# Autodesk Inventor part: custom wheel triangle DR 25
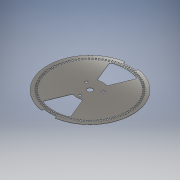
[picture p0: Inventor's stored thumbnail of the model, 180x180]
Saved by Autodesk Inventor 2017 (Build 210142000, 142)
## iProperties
Created: 2016-09
Part Number: custom wheel triangle DR 25
Material: Generic
Document SubType Name: Modeling
Designer: Radek
Density: 1 g/cm^3
Appearance: Mirror
Author: Radek
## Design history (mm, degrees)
workplane "Work Plane1"
sketch "Sketch1"
  geometry: L1 (-46.781, 4.422)-(-44.253, 4.183) reference; L2 (-44.362, 2.791)-(-46.897, 2.951) reference; L3 (-46.411, 7.351)-(-43.903, 6.954) reference; L4 (-44.099, 5.571)-(-46.619, 5.889) reference; L5 (-45.858, 10.251)-(-43.38, 9.696) reference; L6 (-43.663, 8.329)-(-46.158, 8.805) reference; L7 (-45.124, 13.11)-(-42.685, 12.401) reference; L8 (-43.054, 11.054)-(-45.514, 11.686) reference; L9 (-44.212, 15.917)-(-41.822, 15.057) reference; L10 (-42.274, 13.736)-(-44.69, 14.521) reference; L11 (-43.125, 18.662)-(-40.794, 17.653) reference; L12 (-41.329, 16.363)-(-43.69, 17.298) reference; L13 (-41.868, 21.333)-(-39.605, 20.18) reference; L14 (-40.22, 18.926)-(-42.518, 20.007) reference; L15 (-40.446, 23.92)-(-38.26, 22.627) reference; L16 (-38.952, 21.414)-(-41.178, 22.638) reference; L17 (-38.865, 26.412)-(-36.764, 24.985) reference; L18 (-37.53, 23.818)-(-39.675, 25.179) reference; L19 (-37.129, 28.801)-(-35.122, 27.244) reference; L20 (-35.961, 26.127)-(-38.016, 27.62) reference; L21 (-35.248, 31.075)-(-33.342, 29.395) reference; L22 (-34.249, 28.333)-(-36.206, 29.953) reference; L23 (-33.227, 33.227)-(-31.431, 31.431) reference; L24 (-32.403, 30.428)-(-34.254, 32.167) reference; L25 (-31.075, 35.248)-(-29.395, 33.342) reference; L26 (-30.428, 32.403)-(-32.167, 34.254) reference; L27 (-28.801, 37.129)-(-27.244, 35.122) reference; L28 (-28.333, 34.249)-(-29.953, 36.206) reference; L29 (-26.412, 38.865)-(-24.985, 36.764) reference; L30 (-26.127, 35.961)-(-27.62, 38.016) reference; L31 (-23.92, 40.446)-(-22.627, 38.26) reference; L32 (-23.818, 37.53)-(-25.179, 39.675) reference; L33 (-21.333, 41.868)-(-20.18, 39.605) reference; L34 (-21.414, 38.952)-(-22.638, 41.178) reference; L35 (-18.662, 43.125)-(-17.653, 40.794) reference; L36 (-18.926, 40.22)-(-20.007, 42.518) reference; L37 (-15.917, 44.212)-(-15.057, 41.822) reference; L38 (-16.363, 41.329)-(-17.298, 43.69) reference; L39 (-13.11, 45.124)-(-12.401, 42.685) reference; L40 (-13.736, 42.274)-(-14.521, 44.69) reference; L41 (-10.251, 45.858)-(-9.696, 43.38) reference; L42 (-11.054, 43.054)-(-11.686, 45.514) reference; L43 (-7.351, 46.411)-(-6.954, 43.903) reference; L44 (-8.329, 43.663)-(-8.805, 46.158) reference; L45 (-4.422, 46.781)-(-4.183, 44.253) reference; L46 (-5.571, 44.099)-(-5.889, 46.619) reference; L47 (-1.476, 46.967)-(-1.396, 44.428) reference; L48 (-2.791, 44.362)-(-2.951, 46.897) reference; L49 (1.476, 46.967)-(1.396, 44.428) reference; L50 (0, 44.45)-(0, 46.99) reference; L51 (4.422, 46.781)-(4.183, 44.253) reference; L52 (2.791, 44.362)-(2.951, 46.897) reference; L53 (7.351, 46.411)-(6.954, 43.903) reference; L54 (5.571, 44.099)-(5.889, 46.619) reference; L55 (10.251, 45.858)-(9.696, 43.38) reference; L56 (8.329, 43.663)-(8.805, 46.158) reference; L57 (13.11, 45.124)-(12.401, 42.685) reference; L58 (11.054, 43.054)-(11.686, 45.514) reference; L59 (15.917, 44.212)-(15.057, 41.822) reference; L60 (13.736, 42.274)-(14.521, 44.69) reference; L61 (18.662, 43.125)-(17.653, 40.794) reference; L62 (16.363, 41.329)-(17.298, 43.69) reference; L63 (21.333, 41.868)-(20.18, 39.605) reference; L64 (18.926, 40.22)-(20.007, 42.518) reference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; C1 r 50.8 at (0, 0) reference; C2 r 2.984 at (0, 0) reference; C3 r 1.524 at (0, 6.553) reference; C4 r 1.524 at (10.339, 5.969) reference; C5 r 2.984 at (0, 0) reference; C6 r 1.524 at (0, -11.938) reference; C7 r 1.524 at (-5.675, -3.277) reference; C8 r 1.524 at (-10.339, 5.969) reference; C9 r 1.524 at (5.675, -3.277) reference; C10 r 50.8 at (0, 0) reference; C11 r 1.524 at (-5.675, -3.277) reference; C12 r 1.524 at (-10.339, 5.969) reference; C13 r 1.524 at (0, 6.553) reference; C14 r 1.524 at (10.339, 5.969) reference; C15 r 1.524 at (5.675, -3.277) reference; C16 r 1.524 at (0, -11.938) reference; C17 r 2.984 at (0, 0) reference; A1 r 17.081 centre (0, 0) between (0, -17.081) and (17.081, 0) reference; A2 r 17.081 centre (0, 0) between (0, 17.081) and (-17.081, 0) reference; A3 r 43.18 centre (0, 0) between (0, 43.18) and (-43.18, 0) reference; A4 r 43.18 centre (0, 0) between (0, -43.18) and (43.18, 0) reference; A5 r 44.45 centre (0, 0) between (-44.253, 4.183) and (-44.362, 2.791) reference; A6 r 46.99 centre (0, 0) between (-46.781, 4.422) and (-46.897, 2.951) reference; A7 r 44.45 centre (0, 0) between (-43.903, 6.954) and (-44.099, 5.571) reference; A8 r 46.99 centre (0, 0) between (-46.411, 7.351) and (-46.619, 5.889) reference; A9 r 44.45 centre (0, 0) between (-43.38, 9.696) and (-43.663, 8.329) reference; A10 r 46.99 centre (0, 0) between (-45.858, 10.251) and (-46.158, 8.805) reference; A11 r 44.45 centre (0, 0) between (-42.685, 12.401) and (-43.054, 11.054) reference; A12 r 46.99 centre (0, 0) between (-45.124, 13.11) and (-45.514, 11.686) reference; A13 r 44.45 centre (0, 0) between (-41.822, 15.057) and (-42.274, 13.736) reference; A14 r 46.99 centre (0, 0) between (-44.212, 15.917) and (-44.69, 14.521) reference; A15 r 44.45 centre (0, 0) between (-40.794, 17.653) and (-41.329, 16.363) reference; A16 r 46.99 centre (0, 0) between (-43.125, 18.662) and (-43.69, 17.298) reference; A17 r 44.45 centre (0, 0) between (-39.605, 20.18) and (-40.22, 18.926) reference; A18 r 46.99 centre (0, 0) between (-41.868, 21.333) and (-42.518, 20.007) reference; A19 r 44.45 centre (0, 0) between (-38.26, 22.627) and (-38.952, 21.414) reference; A20 r 46.99 centre (0, 0) between (-40.446, 23.92) and (-41.178, 22.638) reference; A21 r 44.45 centre (0, 0) between (-36.764, 24.985) and (-37.53, 23.818) reference; A22 r 46.99 centre (0, 0) between (-38.865, 26.412) and (-39.675, 25.179) reference; A23 r 44.45 centre (0, 0) between (-35.122, 27.244) and (-35.961, 26.127) reference; A24 r 46.99 centre (0, 0) between (-37.129, 28.801) and (-38.016, 27.62) reference; A25 r 44.45 centre (0, 0) between (-33.342, 29.395) and (-34.249, 28.333) reference; A26 r 46.99 centre (0, 0) between (-35.248, 31.075) and (-36.206, 29.953) reference; A27 r 44.45 centre (0, 0) between (-31.431, 31.431) and (-32.403, 30.428) reference; A28 r 46.99 centre (0, 0) between (-33.227, 33.227) and (-34.254, 32.167) reference; A29 r 44.45 centre (0, 0) between (-29.395, 33.342) and (-30.428, 32.403) reference; A30 r 46.99 centre (0, 0) between (-31.075, 35.248) and (-32.167, 34.254) reference; A31 r 44.45 centre (0, 0) between (-27.244, 35.122) and (-28.333, 34.249) reference; A32 r 46.99 centre (0, 0) between (-28.801, 37.129) and (-29.953, 36.206) reference; A33 r 44.45 centre (0, 0) between (-24.985, 36.764) and (-26.127, 35.961) reference; A34 r 46.99 centre (0, 0) between (-26.412, 38.865) and (-27.62, 38.016) reference; A35 r 44.45 centre (0, 0) between (-22.627, 38.26) and (-23.818, 37.53) reference; A36 r 46.99 centre (0, 0) between (-23.92, 40.446) and (-25.179, 39.675) reference; A37 r 44.45 centre (0, 0) between (-20.18, 39.605) and (-21.414, 38.952) reference; A38 r 46.99 centre (0, 0) between (-21.333, 41.868) and (-22.638, 41.178) reference; A39 r 44.45 centre (0, 0) between (-17.653, 40.794) and (-18.926, 40.22) reference; A40 r 46.99 centre (0, 0) between (-18.662, 43.125) and (-20.007, 42.518) reference; A41 r 44.45 centre (0, 0) between (-15.057, 41.822) and (-16.363, 41.329) reference; A42 r 46.99 centre (0, 0) between (-15.917, 44.212) and (-17.298, 43.69) reference; A43 r 44.45 centre (0, 0) between (-12.401, 42.685) and (-13.736, 42.274) reference; A44 r 46.99 centre (0, 0) between (-13.11, 45.124) and (-14.521, 44.69) reference; A45 r 44.45 centre (0, 0) between (-9.696, 43.38) and (-11.054, 43.054) reference; A46 r 46.99 centre (0, 0) between (-10.251, 45.858) and (-11.686, 45.514) reference; A47 r 44.45 centre (0, 0) between (-6.954, 43.903) and (-8.329, 43.663) reference; A48 r 46.99 centre (0, 0) between (-7.351, 46.411) and (-8.805, 46.158) reference; A49 r 44.45 centre (0, 0) between (-4.183, 44.253) and (-5.571, 44.099) reference; A50 r 46.99 centre (0, 0) between (-4.422, 46.781) and (-5.889, 46.619) reference; A51 r 44.45 centre (0, 0) between (-1.396, 44.428) and (-2.791, 44.362) reference; A52 r 46.99 centre (0, 0) between (-1.476, 46.967) and (-2.951, 46.897) reference; A53 r 44.45 centre (0, 0) between (1.396, 44.428) and (0, 44.45) reference; A54 r 46.99 centre (0, 0) between (1.476, 46.967) and (0, 46.99) reference; A55 r 44.45 centre (0, 0) between (4.183, 44.253) and (2.791, 44.362) reference; A56 r 46.99 centre (0, 0) between (4.422, 46.781) and (2.951, 46.897) reference; A57 r 44.45 centre (0, 0) between (6.954, 43.903) and (5.571, 44.099) reference; A58 r 46.99 centre (0, 0) between (7.351, 46.411) and (5.889, 46.619) reference; A59 r 44.45 centre (0, 0) between (9.696, 43.38) and (8.329, 43.663) reference; A60 r 46.99 centre (0, 0) between (10.251, 45.858) and (8.805, 46.158) reference; A61 r 44.45 centre (0, 0) between (12.401, 42.685) and (11.054, 43.054) reference; A62 r 46.99 centre (0, 0) between (13.11, 45.124) and (11.686, 45.514) reference; A63 r 44.45 centre (0, 0) between (15.057, 41.822) and (13.736, 42.274) reference; A64 r 46.99 centre (0, 0) between (15.917, 44.212) and (14.521, 44.69) reference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; 1 further point
  constraints: 8 end point, 2 collinear, 1 parallel
extrude "Extrusion2" new body sketch "Sketch1" distance "d2" = 0.3; taper "d3" = 0 deg
sketch "Sketch2"
  geometry: L1 (-46.781, 4.422)-(-44.253, 4.183) reference; L2 (-44.362, 2.791)-(-46.897, 2.951) reference; L3 (-46.411, 7.351)-(-43.903, 6.954) reference; L4 (-44.099, 5.571)-(-46.619, 5.889) reference; L5 (-45.858, 10.251)-(-43.38, 9.696) reference; L6 (-43.663, 8.329)-(-46.158, 8.805) reference; L7 (-45.124, 13.11)-(-42.685, 12.401) reference; L8 (-43.054, 11.054)-(-45.514, 11.686) reference; L9 (-44.212, 15.917)-(-41.822, 15.057) reference; L10 (-42.274, 13.736)-(-44.69, 14.521) reference; L11 (-43.125, 18.662)-(-40.794, 17.653) reference; L12 (-41.329, 16.363)-(-43.69, 17.298) reference; L13 (-41.868, 21.333)-(-39.605, 20.18) reference; L14 (-40.22, 18.926)-(-42.518, 20.007) reference; L15 (-40.446, 23.92)-(-38.26, 22.627) reference; L16 (-38.952, 21.414)-(-41.178, 22.638) reference; L17 (-38.865, 26.412)-(-36.764, 24.985) reference; L18 (-37.53, 23.818)-(-39.675, 25.179) reference; L19 (-37.129, 28.801)-(-35.122, 27.244) reference; L20 (-35.961, 26.127)-(-38.016, 27.62) reference; L21 (-35.248, 31.075)-(-33.342, 29.395) reference; L22 (-34.249, 28.333)-(-36.206, 29.953) reference; L23 (-33.227, 33.227)-(-31.431, 31.431) reference; L24 (-32.403, 30.428)-(-34.254, 32.167) reference; L25 (-31.075, 35.248)-(-29.395, 33.342) reference; L26 (-30.428, 32.403)-(-32.167, 34.254) reference; L27 (-28.801, 37.129)-(-27.244, 35.122) reference; L28 (-28.333, 34.249)-(-29.953, 36.206) reference; L29 (-26.412, 38.865)-(-24.985, 36.764) reference; L30 (-26.127, 35.961)-(-27.62, 38.016) reference; L31 (-23.92, 40.446)-(-22.627, 38.26) reference; L32 (-23.818, 37.53)-(-25.179, 39.675) reference; L33 (-21.333, 41.868)-(-20.18, 39.605) reference; L34 (-21.414, 38.952)-(-22.638, 41.178) reference; L35 (-18.662, 43.125)-(-17.653, 40.794) reference; L36 (-18.926, 40.22)-(-20.007, 42.518) reference; L37 (-15.917, 44.212)-(-15.057, 41.822) reference; L38 (-16.363, 41.329)-(-17.298, 43.69) reference; L39 (-13.11, 45.124)-(-12.401, 42.685) reference; L40 (-13.736, 42.274)-(-14.521, 44.69) reference; L41 (-10.251, 45.858)-(-9.696, 43.38) reference; L42 (-11.054, 43.054)-(-11.686, 45.514) reference; L43 (-7.351, 46.411)-(-6.954, 43.903) reference; L44 (-8.329, 43.663)-(-8.805, 46.158) reference; L45 (-4.422, 46.781)-(-4.183, 44.253) reference; L46 (-5.571, 44.099)-(-5.889, 46.619) reference; L47 (-1.476, 46.967)-(-1.396, 44.428) reference; L48 (-2.791, 44.362)-(-2.951, 46.897) reference; L49 (1.476, 46.967)-(1.396, 44.428) reference; L50 (0, 44.45)-(0, 46.99) reference; L51 (4.422, 46.781)-(4.183, 44.253) reference; L52 (2.791, 44.362)-(2.951, 46.897) reference; L53 (7.351, 46.411)-(6.954, 43.903) reference; L54 (5.571, 44.099)-(5.889, 46.619) reference; L55 (10.251, 45.858)-(9.696, 43.38) reference; L56 (8.329, 43.663)-(8.805, 46.158) reference; L57 (13.11, 45.124)-(12.401, 42.685) reference; L58 (11.054, 43.054)-(11.686, 45.514) reference; L59 (15.917, 44.212)-(15.057, 41.822) reference; L60 (13.736, 42.274)-(14.521, 44.69) reference; L61 (18.662, 43.125)-(17.653, 40.794) reference; L62 (16.363, 41.329)-(17.298, 43.69) reference; L63 (21.333, 41.868)-(20.18, 39.605) reference; L64 (18.926, 40.22)-(20.007, 42.518) reference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; C1 r 50.8 at (0, 0) reference; C2 r 1.524 at (-5.675, -3.277) reference; C3 r 1.524 at (-10.339, 5.969) reference; C4 r 1.524 at (0, 6.553) reference; C5 r 1.524 at (10.339, 5.969) reference; C6 r 1.524 at (5.675, -3.277) reference; C7 r 1.524 at (0, -11.938) reference; C8 r 2.984 at (0, 0) reference; A1 r 44.45 centre (0, 0) between (-44.253, 4.183) and (-44.362, 2.791) reference; A2 r 46.99 centre (0, 0) between (-46.781, 4.422) and (-46.897, 2.951) reference; A3 r 44.45 centre (0, 0) between (-43.903, 6.954) and (-44.099, 5.571) reference; A4 r 46.99 centre (0, 0) between (-46.411, 7.351) and (-46.619, 5.889) reference; A5 r 44.45 centre (0, 0) between (-43.38, 9.696) and (-43.663, 8.329) reference; A6 r 46.99 centre (0, 0) between (-45.858, 10.251) and (-46.158, 8.805) reference; A7 r 44.45 centre (0, 0) between (-42.685, 12.401) and (-43.054, 11.054) reference; A8 r 46.99 centre (0, 0) between (-45.124, 13.11) and (-45.514, 11.686) reference; A9 r 44.45 centre (0, 0) between (-41.822, 15.057) and (-42.274, 13.736) reference; A10 r 46.99 centre (0, 0) between (-44.212, 15.917) and (-44.69, 14.521) reference; A11 r 44.45 centre (0, 0) between (-40.794, 17.653) and (-41.329, 16.363) reference; A12 r 46.99 centre (0, 0) between (-43.125, 18.662) and (-43.69, 17.298) reference; A13 r 44.45 centre (0, 0) between (-39.605, 20.18) and (-40.22, 18.926) reference; A14 r 46.99 centre (0, 0) between (-41.868, 21.333) and (-42.518, 20.007) reference; A15 r 44.45 centre (0, 0) between (-38.26, 22.627) and (-38.952, 21.414) reference; A16 r 46.99 centre (0, 0) between (-40.446, 23.92) and (-41.178, 22.638) reference; A17 r 44.45 centre (0, 0) between (-36.764, 24.985) and (-37.53, 23.818) reference; A18 r 46.99 centre (0, 0) between (-38.865, 26.412) and (-39.675, 25.179) reference; A19 r 44.45 centre (0, 0) between (-35.122, 27.244) and (-35.961, 26.127) reference; A20 r 46.99 centre (0, 0) between (-37.129, 28.801) and (-38.016, 27.62) reference; A21 r 44.45 centre (0, 0) between (-33.342, 29.395) and (-34.249, 28.333) reference; A22 r 46.99 centre (0, 0) between (-35.248, 31.075) and (-36.206, 29.953) reference; A23 r 44.45 centre (0, 0) between (-31.431, 31.431) and (-32.403, 30.428) reference; A24 r 46.99 centre (0, 0) between (-33.227, 33.227) and (-34.254, 32.167) reference; A25 r 44.45 centre (0, 0) between (-29.395, 33.342) and (-30.428, 32.403) reference; A26 r 46.99 centre (0, 0) between (-31.075, 35.248) and (-32.167, 34.254) reference; A27 r 44.45 centre (0, 0) between (-27.244, 35.122) and (-28.333, 34.249) reference; A28 r 46.99 centre (0, 0) between (-28.801, 37.129) and (-29.953, 36.206) reference; A29 r 44.45 centre (0, 0) between (-24.985, 36.764) and (-26.127, 35.961) reference; A30 r 46.99 centre (0, 0) between (-26.412, 38.865) and (-27.62, 38.016) reference; A31 r 44.45 centre (0, 0) between (-22.627, 38.26) and (-23.818, 37.53) reference; A32 r 46.99 centre (0, 0) between (-23.92, 40.446) and (-25.179, 39.675) reference; A33 r 44.45 centre (0, 0) between (-20.18, 39.605) and (-21.414, 38.952) reference; A34 r 46.99 centre (0, 0) between (-21.333, 41.868) and (-22.638, 41.178) reference; A35 r 44.45 centre (0, 0) between (-17.653, 40.794) and (-18.926, 40.22) reference; A36 r 46.99 centre (0, 0) between (-18.662, 43.125) and (-20.007, 42.518) reference; A37 r 44.45 centre (0, 0) between (-15.057, 41.822) and (-16.363, 41.329) reference; A38 r 46.99 centre (0, 0) between (-15.917, 44.212) and (-17.298, 43.69) reference; A39 r 44.45 centre (0, 0) between (-12.401, 42.685) and (-13.736, 42.274) reference; A40 r 46.99 centre (0, 0) between (-13.11, 45.124) and (-14.521, 44.69) reference; A41 r 44.45 centre (0, 0) between (-9.696, 43.38) and (-11.054, 43.054) reference; A42 r 46.99 centre (0, 0) between (-10.251, 45.858) and (-11.686, 45.514) reference; A43 r 44.45 centre (0, 0) between (-6.954, 43.903) and (-8.329, 43.663) reference; A44 r 46.99 centre (0, 0) between (-7.351, 46.411) and (-8.805, 46.158) reference; A45 r 44.45 centre (0, 0) between (-4.183, 44.253) and (-5.571, 44.099) reference; A46 r 46.99 centre (0, 0) between (-4.422, 46.781) and (-5.889, 46.619) reference; A47 r 44.45 centre (0, 0) between (-1.396, 44.428) and (-2.791, 44.362) reference; A48 r 46.99 centre (0, 0) between (-1.476, 46.967) and (-2.951, 46.897) reference; A49 r 44.45 centre (0, 0) between (1.396, 44.428) and (0, 44.45) reference; A50 r 46.99 centre (0, 0) between (1.476, 46.967) and (0, 46.99) reference; A51 r 44.45 centre (0, 0) between (4.183, 44.253) and (2.791, 44.362) reference; A52 r 46.99 centre (0, 0) between (4.422, 46.781) and (2.951, 46.897) reference; A53 r 44.45 centre (0, 0) between (6.954, 43.903) and (5.571, 44.099) reference; A54 r 46.99 centre (0, 0) between (7.351, 46.411) and (5.889, 46.619) reference; A55 r 44.45 centre (0, 0) between (9.696, 43.38) and (8.329, 43.663) reference; A56 r 46.99 centre (0, 0) between (10.251, 45.858) and (8.805, 46.158) reference; A57 r 44.45 centre (0, 0) between (12.401, 42.685) and (11.054, 43.054) reference; A58 r 46.99 centre (0, 0) between (13.11, 45.124) and (11.686, 45.514) reference; A59 r 44.45 centre (0, 0) between (15.057, 41.822) and (13.736, 42.274) reference; A60 r 46.99 centre (0, 0) between (15.917, 44.212) and (14.521, 44.69) reference; A61 r 44.45 centre (0, 0) between (17.653, 40.794) and (16.363, 41.329) reference; A62 r 46.99 centre (0, 0) between (18.662, 43.125) and (17.298, 43.69) reference; A63 r 44.45 centre (0, 0) between (20.18, 39.605) and (18.926, 40.22) reference; A64 r 46.99 centre (0, 0) between (21.333, 41.868) and (20.007, 42.518) reference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; 1 further point
  constraints: 8 end point, 1 collinear
extrude "Extrusion3" cut sketch "Sketch2" stored distance "d4" = 0.254; taper "d5" = 0 deg
sketch "Sketch3" dims "d20" = 9.26667 (= 0.5 x holediameter), "d21" = 13.10505 (= 1.41421 x d20)
  geometry: L1 (-10.339, 5.969)-(10.339, 5.969); L2 (0, 0)-(50.8, 0); L3 (0, 44.45)-(0, 46.99) reference; L4 (0, 0)-(0, 50.8); L5 (0, 30)-(0, 16.895); L6 (0, 50.165)-(0, 48.26) reference; L7 (-48.26, 0)-(-50.165, 0) reference; L8 (0, 0)-(20.689, 27.504); L9 (0, 50.8)-(0, 50.165); L10 (5.221, 16.068)-(13.32, 40.995); L11 (-5.221, 16.068)-(-13.32, 40.995); C1 r 2.984 at (0, 0) reference; C2 r 15.25 at (0, 0); C3 r 1.524 at (-10.339, 5.969) reference; C4 r 1.524 at (0, -11.938) reference; C5 r 1.524 at (10.339, 5.969) reference; C6 r 1.524 at (-5.675, -3.277) reference; C7 r 1.524 at (5.675, -3.277) reference; A1 r 50.8 centre (0, 0) between (50.8, 0) and (0, 50.8) reference; A2 r 48.26 centre (0, 0) between (0, 48.26) and (-48.26, 0) reference; A3 r 50.165 centre (0, 0) between (0, 50.165) and (-50.165, 0) reference; A4 r 50.165 centre (0, 0) between (-20.154, -45.939) and (22.037, -45.066); A5 r 48.26 centre (0, 0) between (-19.033, -44.348) and (20.956, -43.472); 3 further points; 3 other entities
  constraints: 16 end point, 8 point on circle, 3 centre point, 3 coincident, 2 midpoint, 2 vertical, 1 collinear, 1 horizontal, 1 parallel, 1 point on line, 1 vertical alignment, 19 other
  dimensions: "d9" = 30.5 diameter of C2; "d18" = 0 distance between parallel lines of L4 L5; "d19" = 30 distance of point (0, 0) L5.start (= offaxis); "d24" = 18 deg dimension on point (0, 0) L5.start point (-9.271, 28.532) (= 0.5 x angle); "d28" = 18 deg dimension on point (0, 0) point (9.271, 28.532) L5.start (= 0.5 x angle); "d32" = 0.635 distance of L4.end L6.start (derived)
extrude "Extrusion7" cut sketch "Sketch3" stored distance "d40" = 10; taper "d41" = 0 deg
sketch "Sketch4"
  geometry: L1 (-3.221, 42.985)-(-1.263, 16.848) reference; L2 (1.263, 16.848)-(3.221, 42.985) reference; L3 (3.221, 42.985)-(1.263, 16.848) reference; L4 (-1.263, 16.848)-(-3.221, 42.985) reference; L5 (-1.263, 16.848)-(-3.221, 42.985); L6 (1.263, 16.848)-(3.221, 42.985); C1 r 2.984 at (0, 0) reference; C2 r 50.8 at (0, 0) reference; A1 r 16.895 centre (0, 0) between (1.263, 16.848) and (-1.263, 16.848); A2 r 43.105 centre (0, 0) between (3.221, 42.985) and (-3.221, 42.985); 3 further points; 2 other entities
  constraints: 4 end point, 4 point on circle, 2 centre point, 2 coincident, 2 collinear, 2 other
extrude "Extrusion8" cut sketch "Sketch4" stored distance "d42" = 10; taper "d43" = 0 deg
sketch "Sketch5"
  geometry: L1 (0, 0)-(-7.947, 50.175); L2 (0, 0)-(7.947, 50.175); L3 (7.524, 47.508)-(7.837, 49.483); L4 (-7.524, 47.508)-(-7.837, 49.483); L5 (6.954, 43.903)-(7.351, 46.411) reference; L6 (4.422, 46.781)-(4.183, 44.253) reference; L7 (7.351, 46.411)-(6.954, 43.903) reference; C1 r 2.984 at (0, 0) reference; A1 r 50.8 centre (0, 0) between (-7.947, 50.175) and (7.947, 50.175) reference; A2 r 16.895 centre (0, 0) between (1.263, 16.848) and (-1.263, 16.848) reference; A3 r 43.105 centre (0, 0) between (3.221, 42.985) and (-3.221, 42.985) reference; A4 r 48.1 centre (0, 0) between (7.524, 47.508) and (-7.524, 47.508); A5 r 50.1 centre (0, 0) between (7.837, 49.483) and (-7.837, 49.483); 4 further points; 2 other entities
  constraints: 8 end point, 6 point on circle, 3 point on line, 2 centre point, 2 coincident, 2 collinear, 1 midpoint, 8 other
  dimensions: "d44" = 0.7 radial gap between concentric circles of A1 A5; "d45" = 2 radial gap between concentric circles of A5 A4; "d53" = 18 deg angle of L1 L2
extrude "Extrusion9" cut sketch "Sketch5" stored distance "d46" = 10; taper "d47" = 0 deg
pattern_circular "Circular Pattern3" dims angle "d49" = 360 deg
sketch "Sketch6"
  geometry: L1 (16.895, 0)-(16.848, 0) reference; L2 (42.985, 0)-(43.105, 0) reference; L3 (16.848, -0.3)-(16.895, -0.3) reference; L4 (43.105, -0.3)-(42.985, -0.3) reference; L5 (-50.8, 0)-(50.8, 0) reference; L6 (-50.8, -0.3)-(50.8, -0.3) reference; L7 (16.895, 0)-(43.105, 0); L8 (16.895, -0.3)-(43.105, -0.3); L9 (30, -0.3)-(30, 0); L10 (30, -0.15)-(32.935, -3.085); 1 further point
  constraints: 8 end point, 3 midpoint, 1 collinear, 1 parallel
  dimensions: "d51" = 135 deg angle of L10 L9
workaxis "Work Axis1"
workplane "Work Plane3"
  workplane "Work Plane2"
sketch "Sketch7"
  geometry: L1 (0, -11.938)-(-10.339, 5.969); C1 r 1.524 at (0, -11.938) reference; C2 r 1.524 at (-10.339, 5.969) reference; C3 r 2.984 at (0, 0) reference; C4 r 10.414 at (0, 0); 2 further points
  constraints: 2 end point, 1 centre point, 1 coincident, 1 tangent, 1 other
extrude "Extrusion11" cut sketch "Sketch7" stored distance "d57" = 10; taper "d58" = 0 deg
sketch "Sketch8"
  geometry: L1 (7.837, 49.483)-(7.524, 47.508) reference; L2 (-7.524, 47.508)-(-7.837, 49.483) reference; L3 (-46.967, -1.476)-(-44.428, -1.396) reference; L4 (-44.428, -1.396)-(-44.362, -2.791) reference; L5 (-44.362, -2.791)-(-46.897, -2.951) reference; L6 (-46.897, -2.951)-(-46.967, -1.476) reference; L7 (-46.781, -4.422)-(-44.253, -4.183) reference; L8 (-44.253, -4.183)-(-44.099, -5.571) reference; L9 (-44.099, -5.571)-(-46.619, -5.889) reference; L10 (-46.619, -5.889)-(-46.781, -4.422) reference; L11 (-46.411, -7.351)-(-43.903, -6.954) reference; L12 (-43.903, -6.954)-(-43.663, -8.329) reference; L13 (-43.663, -8.329)-(-46.158, -8.805) reference; L14 (-46.158, -8.805)-(-46.411, -7.351) reference; L15 (-45.858, -10.251)-(-43.38, -9.696) reference; L16 (-43.38, -9.696)-(-43.054, -11.054) reference; L17 (-43.054, -11.054)-(-45.514, -11.686) reference; L18 (-45.514, -11.686)-(-45.858, -10.251) reference; L19 (-45.124, -13.11)-(-42.685, -12.401) reference; L20 (-42.685, -12.401)-(-42.274, -13.736) reference; L21 (-42.274, -13.736)-(-44.69, -14.521) reference; L22 (-44.69, -14.521)-(-45.124, -13.11) reference; L23 (-44.212, -15.917)-(-41.822, -15.057) reference; L24 (-41.822, -15.057)-(-41.329, -16.363) reference; L25 (-41.329, -16.363)-(-43.69, -17.298) reference; L26 (-43.69, -17.298)-(-44.212, -15.917) reference; L27 (-43.125, -18.662)-(-40.794, -17.653) reference; L28 (-40.794, -17.653)-(-40.22, -18.926) reference; L29 (-40.22, -18.926)-(-42.518, -20.007) reference; L30 (-42.518, -20.007)-(-43.125, -18.662) reference; L31 (-41.868, -21.333)-(-39.605, -20.18) reference; L32 (-39.605, -20.18)-(-38.952, -21.414) reference; L33 (-38.952, -21.414)-(-41.178, -22.638) reference; L34 (-41.178, -22.638)-(-41.868, -21.333) reference; L35 (-40.446, -23.92)-(-38.26, -22.627) reference; L36 (-38.26, -22.627)-(-37.53, -23.818) reference; L37 (-37.53, -23.818)-(-39.675, -25.179) reference; L38 (-39.675, -25.179)-(-40.446, -23.92) reference; L39 (-38.865, -26.412)-(-36.764, -24.985) reference; L40 (-36.764, -24.985)-(-35.961, -26.127) reference; L41 (-35.961, -26.127)-(-38.016, -27.62) reference; L42 (-38.016, -27.62)-(-38.865, -26.412) reference; L43 (-37.129, -28.801)-(-35.122, -27.244) reference; L44 (-35.122, -27.244)-(-34.249, -28.333) reference; L45 (-34.249, -28.333)-(-36.206, -29.953) reference; L46 (-36.206, -29.953)-(-37.129, -28.801) reference; L47 (-35.248, -31.075)-(-33.342, -29.395) reference; L48 (-33.342, -29.395)-(-32.403, -30.428) reference; L49 (-32.403, -30.428)-(-34.254, -32.167) reference; L50 (-34.254, -32.167)-(-35.248, -31.075) reference; L51 (-33.227, -33.227)-(-31.431, -31.431) reference; L52 (-31.431, -31.431)-(-30.428, -32.403) reference; L53 (-30.428, -32.403)-(-32.167, -34.254) reference; L54 (-32.167, -34.254)-(-33.227, -33.227) reference; L55 (-31.075, -35.248)-(-29.395, -33.342) reference; L56 (-29.395, -33.342)-(-28.333, -34.249) reference; L57 (-28.333, -34.249)-(-29.953, -36.206) reference; L58 (-29.953, -36.206)-(-31.075, -35.248) reference; L59 (-28.801, -37.129)-(-27.244, -35.122) reference; L60 (-27.244, -35.122)-(-26.127, -35.961) reference; L61 (-26.127, -35.961)-(-27.62, -38.016) reference; L62 (-27.62, -38.016)-(-28.801, -37.129) reference; L63 (-26.412, -38.865)-(-24.985, -36.764) reference; L64 (-24.985, -36.764)-(-23.818, -37.53) reference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; C1 r 2.984 at (0, 0) reference; C2 r 1.524 at (5.675, -3.277) reference; C3 r 1.524 at (-10.339, 5.969) reference; C4 r 1.524 at (-5.675, -3.277) reference; C5 r 1.524 at (0, -11.938) reference; C6 r 1.524 at (10.339, 5.969) reference; C7 r 1.524 at (0, 6.553) reference; C8 r 50.8 at (0, 0) reference; C9 r 2.984 at (0, 0) reference; A1 r 48.1 centre (0, 0) between (7.524, 47.508) and (-7.524, 47.508) reference; A2 r 50.1 centre (0, 0) between (7.837, 49.483) and (-7.837, 49.483) reference; A3 r 43.105 centre (0, 0) between (3.221, 42.985) and (-3.221, 42.985) reference; A4 r 16.895 centre (0, 0) between (1.263, 16.848) and (-1.263, 16.848) reference; A5 r 43.105 centre (0, 0) between (-3.221, -42.985) and (3.221, -42.985); A6 r 16.895 centre (0, 0) between (-1.263, -16.848) and (1.263, -16.848); 3 further points; 1 other entity
  constraints: 8 end point, 4 point on circle, 2 centre point, 2 coincident, 2 collinear, 2 point on line, 2 other
extrude "Extrusion12" cut sketch "Sketch8" stored distance "d59" = 10; taper "d60" = 0 deg
pattern_circular "Circular Pattern4" dims angle "d62" = 360 deg
sketch "Sketch9"
  geometry: L1 (-44.45, 0)-(-46.99, 0) reference; L2 (-46.99, 0)-(-46.967, 1.476) reference; L3 (-46.967, 1.476)-(-44.428, 1.396) reference; L4 (-44.428, 1.396)-(-44.45, 0) reference; L5 (-46.781, 4.422)-(-44.253, 4.183) reference; L6 (-44.253, 4.183)-(-44.362, 2.791) reference; L7 (-44.362, 2.791)-(-46.897, 2.951) reference; L8 (-46.897, 2.951)-(-46.781, 4.422) reference; L9 (-46.411, 7.351)-(-43.903, 6.954) reference; L10 (-43.903, 6.954)-(-44.099, 5.571) reference; L11 (-44.099, 5.571)-(-46.619, 5.889) reference; L12 (-46.619, 5.889)-(-46.411, 7.351) reference; L13 (-45.858, 10.251)-(-43.38, 9.696) reference; L14 (-43.38, 9.696)-(-43.663, 8.329) reference; L15 (-43.663, 8.329)-(-46.158, 8.805) reference; L16 (-46.158, 8.805)-(-45.858, 10.251) reference; L17 (-45.124, 13.11)-(-42.685, 12.401) reference; L18 (-42.685, 12.401)-(-43.054, 11.054) reference; L19 (-43.054, 11.054)-(-45.514, 11.686) reference; L20 (-45.514, 11.686)-(-45.124, 13.11) reference; L21 (-44.212, 15.917)-(-41.822, 15.057) reference; L22 (-41.822, 15.057)-(-42.274, 13.736) reference; L23 (-42.274, 13.736)-(-44.69, 14.521) reference; L24 (-44.69, 14.521)-(-44.212, 15.917) reference; L25 (-43.125, 18.662)-(-40.794, 17.653) reference; L26 (-40.794, 17.653)-(-41.329, 16.363) reference; L27 (-41.329, 16.363)-(-43.69, 17.298) reference; L28 (-43.69, 17.298)-(-43.125, 18.662) reference; L29 (-41.868, 21.333)-(-39.605, 20.18) reference; L30 (-39.605, 20.18)-(-40.22, 18.926) reference; L31 (-40.22, 18.926)-(-42.518, 20.007) reference; L32 (-42.518, 20.007)-(-41.868, 21.333) reference; L33 (-40.446, 23.92)-(-38.26, 22.627) reference; L34 (-38.26, 22.627)-(-38.952, 21.414) reference; L35 (-38.952, 21.414)-(-41.178, 22.638) reference; L36 (-41.178, 22.638)-(-40.446, 23.92) reference; L37 (-38.865, 26.412)-(-36.764, 24.985) reference; L38 (-36.764, 24.985)-(-37.53, 23.818) reference; L39 (-37.53, 23.818)-(-39.675, 25.179) reference; L40 (-39.675, 25.179)-(-38.865, 26.412) reference; L41 (-37.129, 28.801)-(-35.122, 27.244) reference; L42 (-35.122, 27.244)-(-35.961, 26.127) reference; L43 (-35.961, 26.127)-(-38.016, 27.62) reference; L44 (-38.016, 27.62)-(-37.129, 28.801) reference; L45 (-35.248, 31.075)-(-33.342, 29.395) reference; L46 (-33.342, 29.395)-(-34.249, 28.333) reference; L47 (-34.249, 28.333)-(-36.206, 29.953) reference; L48 (-36.206, 29.953)-(-35.248, 31.075) reference; L49 (-33.227, 33.227)-(-31.431, 31.431) reference; L50 (-31.431, 31.431)-(-32.403, 30.428) reference; L51 (-32.403, 30.428)-(-34.254, 32.167) reference; L52 (-34.254, 32.167)-(-33.227, 33.227) reference; L53 (-31.075, 35.248)-(-29.395, 33.342) reference; L54 (-29.395, 33.342)-(-30.428, 32.403) reference; L55 (-30.428, 32.403)-(-32.167, 34.254) reference; L56 (-32.167, 34.254)-(-31.075, 35.248) reference; L57 (-28.801, 37.129)-(-27.244, 35.122) reference; L58 (-27.244, 35.122)-(-28.333, 34.249) reference; L59 (-28.333, 34.249)-(-29.953, 36.206) reference; L60 (-29.953, 36.206)-(-28.801, 37.129) reference; L61 (-26.412, 38.865)-(-24.985, 36.764) reference; L62 (-24.985, 36.764)-(-26.127, 35.961) reference; L63 (-26.127, 35.961)-(-27.62, 38.016) reference; L64 (-27.62, 38.016)-(-26.412, 38.865) reference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; C1 r 50.8 at (0, 0) reference; C2 r 1.524 at (0, 6.553) reference; C3 r 1.524 at (10.339, 5.969) reference; C4 r 1.524 at (0, -11.938) reference; C5 r 1.524 at (-5.675, -3.277) reference; C6 r 1.524 at (-10.339, 5.969) reference; C7 r 1.524 at (5.675, -3.277) reference; C8 r 2.984 at (0, 0) reference; C9 r 2.984 at (0, 0) reference; A1 r 16.895 centre (0, 0) between (1.263, 16.848) and (-1.263, 16.848) reference; A2 r 48.1 centre (0, 0) between (7.524, 47.508) and (-7.524, 47.508) reference; A3 r 50.1 centre (0, 0) between (7.837, 49.483) and (-7.837, 49.483) reference; A4 r 48.1 centre (0, 0) between (-7.524, -47.508) and (7.524, -47.508); A5 r 55.8 centre (0, 0) between (-8.729, -55.113) and (8.729, -55.113); A6 r 43.105 centre (0, 0) between (3.221, 42.985) and (-3.221, 42.985) reference; 2 further points
  constraints: 8 end point, 4 point on circle, 4 point on line, 2 centre point, 2 coincident, 2 collinear
  dimensions: "d64" = 5 radial gap between concentric circles of C1 A5
extrude "Extrusion13" cut sketch "Sketch9" stored distance "d65" = 10; taper "d66" = 0 deg
pattern_circular "Circular Pattern5" dims angle "d68" = 360 deg
fillet "Fillet1" dims "d70" = 0.5 (derived)
fillet "Fillet3" dims "d72" = 0.5 (derived)
pattern_circular "Circular Pattern7" dims angle "d77" = 360 deg
sketch "Sketch10"
  geometry: C1 r 1.524 at (-5.675, -3.277) reference; C2 r 1.524 at (0, 6.553) reference; C3 r 1.524 at (5.675, -3.277) reference; 1 further point
extrude "Extrusion14" join sketch "Sketch10" stored distance "d79" = 10; taper "d80" = 0 deg
sketch "Sketch11"
  geometry: L1 (7.868, 49.678)-(7.602, 47.999) reference; L2 (-7.602, 47.999)-(-7.868, 49.678) reference; L3 (-7.868, -49.678)-(-7.602, -47.999) reference; L4 (7.602, -47.999)-(7.868, -49.678) reference; L5 (-44.942, 0)-(-46.482, 0) reference; L6 (-46.982, 0.508)-(-46.975, 0.968) reference; L7 (-46.459, 1.46)-(-44.92, 1.412) reference; L8 (-44.436, 0.904)-(-44.442, 0.492) reference; L9 (-46.276, 4.374)-(-44.743, 4.229) reference; L10 (-44.291, 3.692)-(-44.324, 3.282) reference; L11 (-44.854, 2.822)-(-46.39, 2.919) reference; L12 (-46.857, 3.457)-(-46.821, 3.916) reference; L13 (-45.91, 7.271)-(-44.389, 7.031) reference; L14 (-43.972, 6.466)-(-44.03, 6.058) reference; L15 (-44.588, 5.633)-(-46.116, 5.826) reference; L16 (-46.548, 6.392)-(-46.483, 6.848) reference; L17 (-45.363, 10.14)-(-43.86, 9.804) reference; L18 (-43.479, 9.214)-(-43.563, 8.811) reference; L19 (-44.146, 8.421)-(-45.659, 8.71) reference; L20 (-46.055, 9.302)-(-45.961, 9.753) reference; L21 (-44.636, 12.968)-(-43.158, 12.538) reference; L22 (-42.815, 11.926)-(-42.924, 11.529) reference; L23 (-43.53, 11.177)-(-45.022, 11.56) reference; L24 (-45.38, 12.176)-(-45.258, 12.62) reference; L25 (-43.734, 15.745)-(-42.285, 15.224) reference; L26 (-41.982, 14.591)-(-42.115, 14.201) reference; L27 (-42.743, 13.888)-(-44.207, 14.364) reference; L28 (-44.526, 15.001)-(-44.377, 15.437) reference; L29 (-42.659, 18.46)-(-41.246, 17.849) reference; L30 (-40.983, 17.198)-(-41.14, 16.818) reference; L31 (-41.786, 16.544)-(-43.218, 17.111) reference; L32 (-43.496, 17.767)-(-43.32, 18.193) reference; L33 (-41.416, 21.102)-(-40.044, 20.403) reference; L34 (-39.822, 19.738)-(-40.003, 19.368) reference; L35 (-40.665, 19.135)-(-42.058, 19.791) reference; L36 (-42.294, 20.463)-(-42.092, 20.877) reference; L37 (-40.009, 23.661)-(-38.684, 22.877) reference; L38 (-38.504, 22.199)-(-38.708, 21.841) reference; L39 (-39.383, 21.651)-(-40.733, 22.393) reference; L40 (-40.926, 23.079)-(-40.698, 23.479) reference; L41 (-38.444, 26.127)-(-37.171, 25.261) reference; L42 (-37.034, 24.573)-(-37.26, 24.229) reference; L43 (-37.946, 24.081)-(-39.246, 24.906) reference; L44 (-39.396, 25.603)-(-39.143, 25.988) reference; L45 (-36.728, 28.489)-(-35.511, 27.545) reference; L46 (-35.418, 26.85)-(-35.665, 26.521) reference; L47 (-36.359, 26.416)-(-37.605, 27.321) reference; L48 (-37.711, 28.026)-(-37.434, 28.394) reference; L49 (-34.867, 30.739)-(-33.712, 29.721) reference; L50 (-33.662, 29.021)-(-33.93, 28.708) reference; L51 (-34.629, 28.647)-(-35.815, 29.629) reference; L52 (-35.877, 30.339)-(-35.578, 30.689) reference; L53 (-32.868, 32.868)-(-31.779, 31.779) reference; L54 (-31.773, 31.077)-(-32.06, 30.782) reference; L55 (-32.761, 30.765)-(-33.884, 31.819) reference; L56 (-33.901, 32.532)-(-33.58, 32.862) reference; L57 (-30.739, 34.867)-(-29.721, 33.712) reference; L58 (-29.759, 33.011)-(-30.064, 32.734) reference; L59 (-30.765, 32.761)-(-31.819, 33.884) reference; L60 (-31.791, 34.596)-(-31.451, 34.906) reference; L61 (-28.489, 36.728)-(-27.545, 35.511) reference; L62 (-27.628, 34.815)-(-27.949, 34.557) reference; L63 (-28.647, 34.629)-(-29.629, 35.815) reference; L64 (-29.556, 36.524)-(-29.197, 36.812) reference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; C1 r 1.524 at (10.339, 5.969) reference; C2 r 1.524 at (0, -11.938) reference; C3 r 1.524 at (-10.339, 5.969) reference; C4 r 2.984 at (0, 0) reference; C5 r 2.984 at (0, 0) reference; A1 r 0.5 centre (8.362, 49.6) between (8.445, 50.093) and (7.868, 49.678) reference; A2 r 48.1 centre (0, 0) between (7.035, 47.583) and (-7.035, 47.583) reference; A3 r 0.5 centre (-8.362, 49.6) between (-7.868, 49.678) and (-8.445, 50.093) reference; A4 r 50.8 centre (0, 0) between (-8.445, 50.093) and (-8.445, -50.093) reference; A5 r 0.5 centre (-8.362, -49.6) between (-8.445, -50.093) and (-7.868, -49.678) reference; A6 r 0.5 centre (-7.108, -48.077) between (-7.035, -47.583) and (-7.602, -47.999) reference; A7 r 48.1 centre (0, 0) between (-7.035, -47.583) and (7.035, -47.583) reference; A8 r 0.5 centre (7.108, -48.077) between (7.602, -47.999) and (7.035, -47.583) reference; A9 r 0.5 centre (8.362, -49.6) between (7.868, -49.678) and (8.445, -50.093) reference; A10 r 50.8 centre (0, 0) between (8.445, -50.093) and (8.445, 50.093) reference; A11 r 0.5 centre (-46.482, 0.5) between (-46.982, 0.508) and (-46.482, 0) reference; A12 r 0.5 centre (-46.475, 0.96) between (-46.459, 1.46) and (-46.975, 0.968) reference; A13 r 0.5 centre (-44.936, 0.912) between (-44.436, 0.904) and (-44.92, 1.412) reference; A14 r 0.5 centre (-44.942, 0.5) between (-44.942, 0) and (-44.442, 0.492) reference; A15 r 0.5 centre (-44.79, 3.732) between (-44.291, 3.692) and (-44.743, 4.229) reference; A16 r 0.5 centre (-44.822, 3.321) between (-44.854, 2.822) and (-44.324, 3.282) reference; A17 r 0.5 centre (-46.359, 3.418) between (-46.857, 3.457) and (-46.39, 2.919) reference; A18 r 0.5 centre (-46.323, 3.877) between (-46.276, 4.374) and (-46.821, 3.916) reference; A19 r 0.5 centre (-44.467, 6.537) between (-43.972, 6.466) and (-44.389, 7.031) reference; A20 r 0.5 centre (-44.525, 6.129) between (-44.588, 5.633) and (-44.03, 6.058) reference; A21 r 0.5 centre (-46.053, 6.322) between (-46.548, 6.392) and (-46.116, 5.826) reference; A22 r 0.5 centre (-45.988, 6.778) between (-45.91, 7.271) and (-46.483, 6.848) reference; A23 r 0.5 centre (-43.969, 9.316) between (-43.479, 9.214) and (-43.86, 9.804) reference; A24 r 0.5 centre (-44.052, 8.912) between (-44.146, 8.421) and (-43.563, 8.811) reference; A25 r 0.5 centre (-45.565, 9.201) between (-46.055, 9.302) and (-45.659, 8.71) reference; A26 r 0.5 centre (-45.472, 9.652) between (-45.363, 10.14) and (-45.961, 9.753) reference; A27 r 0.5 centre (-43.297, 12.058) between (-42.815, 11.926) and (-43.158, 12.538) reference; A28 r 0.5 centre (-43.406, 11.661) between (-43.53, 11.177) and (-42.924, 11.529) reference; A29 r 0.5 centre (-44.897, 12.044) between (-45.38, 12.176) and (-45.022, 11.56) reference; A30 r 0.5 centre (-44.776, 12.488) between (-44.636, 12.968) and (-45.258, 12.62) reference; A31 r 0.5 centre (-42.455, 14.753) between (-41.982, 14.591) and (-42.285, 15.224) reference; A32 r 0.5 centre (-42.588, 14.363) between (-42.743, 13.888) and (-42.115, 14.201) reference; A33 r 0.5 centre (-44.053, 14.839) between (-44.526, 15.001) and (-44.207, 14.364) reference; A34 r 0.5 centre (-43.903, 15.275) between (-43.734, 15.745) and (-44.377, 15.437) reference; A35 r 0.5 centre (-41.444, 17.39) between (-40.983, 17.198) and (-41.246, 17.849) reference; A36 r 0.5 centre (-41.602, 17.009) between (-41.786, 16.544) and (-41.14, 16.818) reference; A37 r 0.5 centre (-43.034, 17.576) between (-43.496, 17.767) and (-43.218, 17.111) reference; A38 r 0.5 centre (-42.858, 18.001) between (-42.659, 18.46) and (-43.32, 18.193) reference; A39 r 0.5 centre (-40.271, 19.958) between (-39.822, 19.738) and (-40.044, 20.403) reference; A40 r 0.5 centre (-40.452, 19.588) between (-40.665, 19.135) and (-40.003, 19.368) reference; A41 r 0.5 centre (-41.845, 20.244) between (-42.294, 20.463) and (-42.058, 19.791) reference; A42 r 0.5 centre (-41.643, 20.657) between (-41.416, 21.102) and (-42.092, 20.877) reference; A43 r 0.5 centre (-38.938, 22.447) between (-38.504, 22.199) and (-38.684, 22.877) reference; A44 r 0.5 centre (-39.142, 22.089) between (-39.383, 21.651) and (-38.708, 21.841) reference; A45 r 0.5 centre (-40.492, 22.831) between (-40.926, 23.079) and (-40.733, 22.393) reference; A46 r 0.5 centre (-40.264, 23.231) between (-40.009, 23.661) and (-40.698, 23.479) reference; A47 r 0.5 centre (-37.452, 24.848) between (-37.034, 24.573) and (-37.171, 25.261) reference; A48 r 0.5 centre (-37.678, 24.503) between (-37.946, 24.081) and (-37.26, 24.229) reference; A49 r 0.5 centre (-38.978, 25.329) between (-39.396, 25.603) and (-39.246, 24.906) reference; A50 r 0.5 centre (-38.725, 25.713) between (-38.444, 26.127) and (-39.143, 25.988) reference; A51 r 0.5 centre (-35.818, 27.15) between (-35.418, 26.85) and (-35.511, 27.545) reference; A52 r 0.5 centre (-36.065, 26.821) between (-36.359, 26.416) and (-35.665, 26.521) reference; A53 r 0.5 centre (-37.311, 27.726) between (-37.711, 28.026) and (-37.605, 27.321) reference; A54 r 0.5 centre (-37.035, 28.094) between (-36.728, 28.489) and (-37.434, 28.394) reference; A55 r 0.5 centre (-34.042, 29.346) between (-33.662, 29.021) and (-33.712, 29.721) reference; A56 r 0.5 centre (-34.31, 29.032) between (-34.629, 28.647) and (-33.93, 28.708) reference; A57 r 0.5 centre (-35.496, 30.014) between (-35.877, 30.339) and (-35.815, 29.629) reference; A58 r 0.5 centre (-35.197, 30.364) between (-34.867, 30.739) and (-35.578, 30.689) reference; A59 r 0.5 centre (-32.132, 31.425) between (-31.773, 31.077) and (-31.779, 31.779) reference; A60 r 0.5 centre (-32.419, 31.13) between (-32.761, 30.765) and (-32.06, 30.782) reference; A61 r 0.5 centre (-33.542, 32.184) between (-33.901, 32.532) and (-33.884, 31.819) reference; A62 r 0.5 centre (-33.221, 32.514) between (-32.868, 32.868) and (-33.58, 32.862) reference; A63 r 0.5 centre (-30.096, 33.381) between (-29.759, 33.011) and (-29.721, 33.712) reference; A64 r 0.5 centre (-30.401, 33.104) between (-30.765, 32.761) and (-30.064, 32.734) reference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; 1 further point
  constraints: 11 point on circle, 10 end point, 4 centre point, 4 coincident, 4 point on line, 2 collinear, 1 vertical, 1 other
  dimensions: "d81" = 2 dimension on C1 A413; "d82" = 1 distance edge to line of A414 L114; "d85" = 45 deg angle of L406 L407 (derived)
extrude "Extrusion15" cut sketch "Sketch11" stored distance "d83" = 0; taper "d84" = 0 deg
fillet "Fillet4" dims "d86" = 2
body "Solid2"
pattern_circular "Circular Pattern1" dims angle "d7" = 360 deg
pattern_circular "Circular Pattern6" dims angle "d74" = 360 deg
node "Reference1"
node "Reference2"
node "Reference3"
node "Reference4"
node "Reference5"
node "Reference6"
node "Reference7"
node "Reference8"
node "Reference9"
node "Reference10"
node "Reference11"
node "Reference12"
node "Reference13"
node "Reference14"
node "Reference15"
node "Reference16"
node "Reference17"
node "Reference18"
node "Reference19"
node "Projected Loop1"
node "Projected Loop2"
node "Projected Loop3"
other parameters: "d12" = 9.66667 (computed from ftube, FOV), "FOV" = 1.5 [user parameter; used in 2 equation terms], "dutycycle" = 3.96645 (computed from holelength, offaxis) [user parameter], "offaxis" = 30 [user parameter; used in 4 equation terms], "angle" = 36 deg (computed from holediameter, holelength, offaxis) [user parameter; used in 2 equation terms], "holelength" = 37.38289 (computed from dutyratio, offaxis, holediameter) [user parameter; used in 2 equation terms], "holediameter" = 18.53333 (computed from FOV, ftube) [user parameter; used in 3 equation terms], "dutyratio" = 2.5 [user parameter; used in 1 equation term], "d52" = 45 deg, "minradius" = 0.5 [user parameter]
